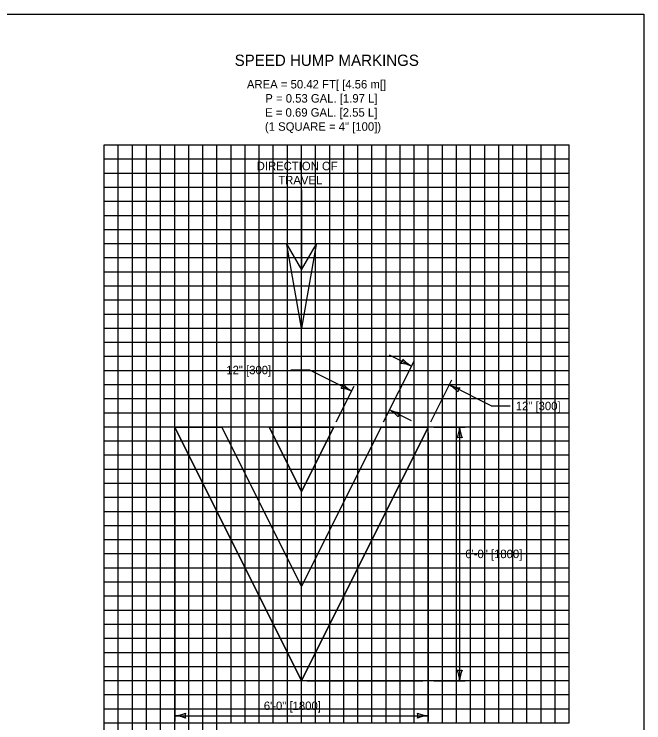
# Model space of a CAD drawing. Extents: x 49948.7 to 50021, y 49977 to 50017.6.
# Drawn here: x 50012.28 to 50016.75, y 49993.97 to 49999 of the extents above; entities that cross this region are included whole.
import ezdxf

# ---------------------------------------------------------------- set-up
doc = ezdxf.new("R2010")
doc.units = 0
for name, color, linetype in [('Level 1', 7, 'Continuous'), ('Level 2', 7, 'Continuous'), ('Level 3', 7, 'Continuous'), ('Level 9', 7, 'Continuous')]:
    doc.layers.add(name, color=color, linetype=linetype)

msp = doc.modelspace()

# ---------------------------------------------------------------- linework, layer by layer
at = {"layer": 'Level 1'}
for p, q in [((50014.3208, 49997.7522), (50014.3205, 49997.1845)), ((50014.3213, 49997.7521), (50014.3209, 49997.1846)), ((50014.3207, 49994.2704), (50013.4207, 49996.0704)), ((50013.4207, 49996.0704), (50013.7561, 49996.0704)), ((50013.7561, 49996.0704), (50013.4207, 49996.0704)), ((50013.4207, 49996.0704), (50014.3207, 49994.2704)), ((50014.3207, 49994.9413), (50013.7561, 49996.0704)), ((50014.3207, 49994.9413), (50013.7561, 49996.0704)), ((50014.3207, 49995.6121), (50014.0915, 49996.0704)), ((50014.0915, 49996.0704), (50014.5498, 49996.0704)), ((50014.5498, 49996.0704), (50014.0915, 49996.0704)), ((50014.0915, 49996.0704), (50014.3207, 49995.6121)), ((50014.5498, 49996.0704), (50014.3207, 49995.6121)), ((50014.8852, 49996.0704), (50014.3207, 49994.9413)), ((50015.2207, 49996.0704), (50014.3207, 49994.2704)), ((50014.3207, 49995.6121), (50014.5498, 49996.0704)), ((50014.3207, 49994.2704), (50015.2207, 49996.0704)), ((50014.8852, 49996.0704), (50014.3207, 49994.9413)), ((50014.8852, 49996.0704), (50015.2207, 49996.0704)), ((50015.2207, 49996.0704), (50014.8852, 49996.0704))]:
    msp.add_line(p, q, dxfattribs=at)
for points in [[(49999.3835, 49998.9992), (50016.7501, 49998.9992), (50016.7501, 49987.7988), (49999.3835, 49987.7988)], [(50014.4257, 49997.366), (50014.3207, 49996.7722), (50014.2157, 49997.3661), (50014.3211, 49997.1849)]]:
    msp.add_lwpolyline(points, close=True, dxfattribs=at)
at = {"layer": 'Level 3'}
for p, q in [((50015.1014, 49996.5029), (50014.9463, 49996.5804)), ((50014.9031, 49996.1062), (50015.1193, 49996.5386)), ((50014.3792, 49996.4749), (50014.2459, 49996.4749)), ((50014.6774, 49996.3258), (50014.3792, 49996.4749)), ((50015.2385, 49996.1062), (50015.3877, 49996.4045)), ((50014.5677, 49996.1062), (50014.6954, 49996.3615)), ((50015.6678, 49996.2197), (50015.3698, 49996.3687)), ((50015.1009, 49996.114), (50014.9458, 49996.1916)), ((50015.6678, 49996.2197), (50015.8011, 49996.2197)), ((50013.4207, 49996.0304), (50013.4207, 49993.9829)), ((50015.2207, 49996.0304), (50015.2207, 49993.9829)), ((50015.2607, 49996.0704), (50015.4828, 49996.0704)), ((50015.4428, 49996.0704), (50015.4428, 49994.2704)), ((50014.3607, 49994.2704), (50015.1807, 49994.2705)), ((50015.2607, 49994.2704), (50015.4828, 49994.2704)), ((50013.4207, 49994.0229), (50015.2207, 49994.0229))]:
    msp.add_line(p, q, dxfattribs=at)
for centre, radius, start, end in [((50014.9868, 49996.5602), 0.0548, 315.5738, 351.2961), ((50015.209, 49996.6975), 0.2223, 220.891, 241.0745), ((50015.0077, 49996.2896), 0.233, 66.2623, 85.5121), ((50014.5628, 49996.3831), 0.0548, 315.5738, 351.2961), ((50014.785, 49996.5203), 0.2223, 220.891, 241.0745), ((50014.5837, 49996.1125), 0.233, 66.2623, 85.5121), ((50015.2623, 49996.1741), 0.2223, 40.891, 61.0745), ((50015.4636, 49996.582), 0.233, 246.2623, 265.5121), ((50015.4845, 49996.3114), 0.0548, 135.5738, 171.2961), ((50014.8383, 49995.997), 0.2223, 40.891, 61.0745), ((50015.0396, 49996.4049), 0.233, 246.2623, 265.5121), ((50015.0605, 49996.1342), 0.0548, 135.5738, 171.2961), ((50015.2207, 49996.0796), 0.2223, 337.456, 357.6395), ((50015.6756, 49996.0819), 0.233, 182.8273, 202.0772), ((50015.4428, 49995.9422), 0.0548, 72.1388, 107.8612), ((50015.4428, 49994.3987), 0.0548, 252.1388, 287.8612), ((50015.2101, 49994.259), 0.233, 2.8273, 22.0772), ((50015.665, 49994.2613), 0.2223, 157.456, 177.6395), ((50013.4092, 49994.2556), 0.233, 272.8273, 292.0772), ((50013.4115, 49993.8007), 0.2223, 67.456, 87.6395), ((50013.5489, 49994.0229), 0.0548, 162.1388, 197.8612), ((50015.2298, 49994.245), 0.2223, 247.456, 267.6395), ((50015.0924, 49994.0229), 0.0548, 342.1388, 17.8612), ((50015.2321, 49993.7902), 0.233, 92.8273, 112.0772)]:
    msp.add_arc(centre, radius, start, end, dxfattribs=at)
at = {"layer": 'Level 9'}
for p, q in [((50012.9207, 49993.9722), (50012.9207, 49998.0722)), ((50012.9207, 49998.0722), (50016.2207, 49998.0722)), ((50013.0207, 49993.9722), (50013.0207, 49998.0722)), ((50013.1207, 49993.9722), (50013.1207, 49998.0722)), ((50013.2207, 49995.4721), (50013.2207, 49998.0722)), ((50013.3207, 49993.9722), (50013.3207, 49998.0722)), ((50013.4207, 49993.9722), (50013.4207, 49998.0722)), ((50013.5207, 49993.9722), (50013.5207, 49998.0722)), ((50013.6207, 49993.9722), (50013.6207, 49998.0722)), ((50013.7207, 49993.9722), (50013.7207, 49998.0722)), ((50013.8207, 49993.9722), (50013.8207, 49998.0722)), ((50013.9207, 49993.9722), (50013.9207, 49998.0722)), ((50014.0207, 49993.9722), (50014.0207, 49998.0722)), ((50014.1207, 49993.9722), (50014.1207, 49998.0722)), ((50014.2207, 49993.9722), (50014.2207, 49998.0722)), ((50014.3207, 49993.9722), (50014.3207, 49998.0722)), ((50014.4207, 49993.9722), (50014.4207, 49998.0722)), ((50014.5207, 49993.9722), (50014.5207, 49998.0722)), ((50014.6207, 49993.9722), (50014.6207, 49998.0722)), ((50014.7207, 49993.9722), (50014.7207, 49998.0722)), ((50014.8207, 49993.9722), (50014.8207, 49998.0722)), ((50014.9207, 49993.9722), (50014.9207, 49998.0722)), ((50015.0207, 49993.9722), (50015.0207, 49998.0722)), ((50015.1207, 49993.9722), (50015.1207, 49998.0722)), ((50015.2207, 49993.9722), (50015.2207, 49998.0722)), ((50015.3207, 49993.9722), (50015.3207, 49998.0722)), ((50015.4207, 49993.9722), (50015.4207, 49998.0722)), ((50015.5207, 49993.9722), (50015.5207, 49998.0722)), ((50015.6207, 49993.9722), (50015.6207, 49998.0722)), ((50015.7207, 49993.9722), (50015.7207, 49998.0722)), ((50015.8207, 49993.9722), (50015.8207, 49998.0722)), ((50015.9207, 49993.9722), (50015.9207, 49998.0722)), ((50016.0207, 49993.9722), (50016.0207, 49998.0722)), ((50016.1207, 49993.9722), (50016.1207, 49998.0722)), ((50016.2207, 49993.9722), (50016.2207, 49998.0722)), ((50012.9207, 49997.9722), (50016.2207, 49997.9722)), ((50012.9207, 49997.8722), (50016.2207, 49997.8722)), ((50012.9207, 49997.7722), (50016.2207, 49997.7722)), ((50012.9207, 49997.6722), (50016.2207, 49997.6722)), ((50012.9207, 49997.5722), (50016.2207, 49997.5722)), ((50012.9207, 49997.4722), (50016.2207, 49997.4722)), ((50012.9207, 49997.3722), (50016.2207, 49997.3722)), ((50012.9207, 49997.2722), (50016.2207, 49997.2722)), ((50012.9207, 49997.1722), (50016.2207, 49997.1722)), ((50012.9207, 49997.0722), (50016.2207, 49997.0722)), ((50012.9207, 49996.9722), (50016.2207, 49996.9722)), ((50012.9207, 49996.8722), (50016.2207, 49996.8722)), ((50012.9207, 49996.7722), (50016.2207, 49996.7722)), ((50012.9207, 49996.6722), (50016.2207, 49996.6722)), ((50012.9207, 49996.5722), (50016.2207, 49996.5722)), ((50012.9207, 49996.4722), (50016.2207, 49996.4722)), ((50012.9207, 49996.3722), (50016.2207, 49996.3722)), ((50012.9207, 49996.2722), (50016.2207, 49996.2722)), ((50012.9207, 49996.1722), (50016.2207, 49996.1722)), ((50012.9207, 49996.0722), (50016.2207, 49996.0722)), ((50012.9207, 49995.9722), (50016.2207, 49995.9722)), ((50012.9207, 49995.8722), (50016.2207, 49995.8722)), ((50012.9207, 49995.7722), (50016.2207, 49995.7722)), ((50012.9207, 49995.6722), (50016.2207, 49995.6722)), ((50012.9207, 49995.5722), (50016.2207, 49995.5722)), ((50012.9207, 49995.4722), (50016.2207, 49995.4722)), ((50013.2207, 49995.4722), (50016.0207, 49995.4722)), ((50013.2207, 49993.9722), (50013.2207, 49995.4722)), ((50012.9207, 49995.3722), (50016.2207, 49995.3722)), ((50012.9207, 49995.2722), (50016.2207, 49995.2722)), ((50012.9207, 49995.1722), (50016.2207, 49995.1722)), ((50012.9207, 49995.0722), (50016.2207, 49995.0722)), ((50012.9207, 49994.9722), (50016.2207, 49994.9722)), ((50012.9207, 49994.8722), (50016.2207, 49994.8722)), ((50012.9207, 49994.7722), (50016.2207, 49994.7722)), ((50012.9207, 49994.6722), (50016.2207, 49994.6722)), ((50012.9207, 49994.5722), (50016.2207, 49994.5722)), ((50012.9207, 49994.4722), (50016.2207, 49994.4722)), ((50012.9207, 49994.3722), (50016.2207, 49994.3722)), ((50012.9207, 49994.2722), (50016.2207, 49994.2722)), ((50012.9207, 49994.1722), (50016.2207, 49994.1722)), ((50012.9207, 49994.0722), (50016.2207, 49994.0722)), ((50012.9207, 49991.5721), (50012.9207, 49993.9722)), ((50012.9207, 49993.9722), (50013.7207, 49993.9722)), ((50013.0207, 49991.5721), (50013.0207, 49993.9722)), ((50013.1207, 49991.5721), (50013.1207, 49993.9722)), ((50013.2207, 49991.5721), (50013.2207, 49993.9722)), ((50013.2207, 49993.9722), (50016.0207, 49993.9722)), ((50013.3207, 49991.5721), (50013.3207, 49993.9722)), ((50013.4207, 49991.5721), (50013.4207, 49993.9722)), ((50013.5207, 49991.5721), (50013.5207, 49993.9722)), ((50013.6207, 49991.5721), (50013.6207, 49993.9722)), ((50013.7207, 49989.5722), (50013.7207, 49993.9722)), ((50013.7207, 49993.9722), (50016.2207, 49993.9722))]:
    msp.add_line(p, q, dxfattribs=at)

# ---------------------------------------------------------------- texts
at = {"layer": 'Level 2'}
for s, height, p in [('SPEED HUMP MARKINGS', 0.08, (50013.8462, 49998.6322)), ('AREA = 50.42 FT[ [4.56 m[]', 0.06, (50013.9333, 49998.4722)), ('P = 0.53 GAL. [1.97 L]', 0.06, (50014.0637, 49998.3722)), ('E = 0.69 GAL. [2.55 L]', 0.06, (50014.0625, 49998.2722)), ('(1 SQUARE = 4" [100])', 0.06, (50014.0609, 49998.1722)), ('DIRECTION OF', 0.06, (50014.0024, 49997.8922)), ('TRAVEL', 0.06, (50014.1559, 49997.7922)), ('12" [300]', 0.06, (50013.7871, 49996.4449)), ('12" [300]', 0.06, (50015.8411, 49996.1897)), ('6\'-0" [1800]', 0.06, (50015.4828, 49995.1404)), ('6\'-0" [1800]', 0.06, (50014.0531, 49994.0629))]:
    msp.add_text(s, height=height, dxfattribs=at).set_placement(p)

doc.saveas('drawing.dxf')
